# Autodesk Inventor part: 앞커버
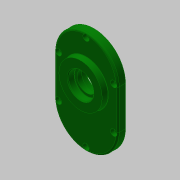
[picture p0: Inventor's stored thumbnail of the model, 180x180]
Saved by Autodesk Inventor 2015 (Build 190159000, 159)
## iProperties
Created: 2016-12
Part Number: 앞커버
Material: 알루미늄 6061
Document SubType Name: Modeling
Designer: mduedu
Density: 2.71 g/cm^3
Mass: 264.838 g
Surface Area: 264.105 cm^2
Volume: 97.726 cm^3
Appearance: 진녹색
Author: mduedu
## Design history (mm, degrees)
sketch "스케치1"
  geometry: L1 (40, -25)-(40, 25); L2 (-40, 25)-(-40, -25); L3 (-40, -25)-(40, 25); L4 (40, -25)-(-40, 25); A1 r 40 centre (0, 25) between (40, 25) and (-40, 25); A2 r 40 centre (0, -25) between (-40, -25) and (40, -25); 1 further point
  constraints: 8 end point, 4 point on circle, 4 tangent, 2 centre point, 2 midpoint, 1 parallel, 1 vertical
  dimensions: "d0" = 130 dimension on A2 A1; "d2" = 80 distance between parallel lines of L1 L2
extrude "돌출1" new body sketch "스케치1" distance "d3" = 10; taper "d4" = 0 deg
sketch "스케치2"
  geometry: C1 r 21 at (0, 11); 1 further point
  constraints: 1 centre point, 1 vertical alignment
  dimensions: "d5" = 42 diameter of C1; "d7" = 11 distance of C1.centre point (0, 0)
extrude "돌출2" join sketch "스케치2" distance "d8" = 7; taper "d9" = 0 deg
sketch "스케치3"
  geometry: C1 r 15 at (0, -33.1); C2 r 21 at (0, 11) reference; 1 further point
  constraints: 1 centre point, 1 vertical alignment
  dimensions: "d10" = 30 diameter of C1; "d71" = 44.1 distance of C1.centre C2.centre
extrude "돌출3" join sketch "스케치3" distance "d12" = 7; taper "d13" = 0 deg
sketch "스케치4"
  geometry: C1 r 28 at (0, 11); A1 r 21 centre (0, 11) between (8.978, -7.984) and (-8.978, -7.984) reference; 1 further point
  constraints: 1 centre point, 1 coincident
  dimensions: "d14" = 56 diameter of C1
extrude "돌출4" join sketch "스케치4" distance "d15" = 7; taper "d16" = -5 deg
hole "구멍1" diameter "d19" = 35; stored, may be unused: countersink angle "d23" = 90 deg, drill point angle "d25" = 0 deg; dims "d17" = 10, "d18" = 10, "d20" = 6, "d21" = 4, "d22" = 2, "d24" = 10
hole "구멍2" diameter "d28" = 22; stored, may be unused: countersink angle "d32" = 90 deg, drill point angle "d34" = 0 deg; dims "d26" = 10, "d27" = 10, "d29" = 6, "d30" = 4, "d31" = 2, "d33" = 7
hole "구멍3" diameter "d37" = 19; stored, may be unused: countersink angle "d41" = 90 deg, drill point angle "d43" = 0 deg; dims "d35" = 10, "d36" = 10, "d38" = 6, "d39" = 4, "d40" = 2, "d42" = 1
hole "구멍4" diameter "d46" = 32; stored, may be unused: countersink angle "d50" = 90 deg, drill point angle "d52" = 0 deg; dims "d44" = 10, "d45" = 10, "d47" = 6, "d48" = 4, "d49" = 2, "d51" = 8
hole "구멍5" diameter "d55" = 25; stored, may be unused: countersink angle "d59" = 90 deg, drill point angle "d61" = 0 deg; dims "d53" = 10, "d54" = 10, "d56" = 6, "d57" = 4, "d58" = 2, "d60" = 8
fillet "모깎기1" dims "d62" = 0.3
fillet "모깎기2" dims "d63" = 2
chamfer "모따기1" distance "d64" = 1; stored, may be unused: second distance "d65" = 2, angle "d66" = 45 deg
fillet "모깎기4" dims "d68" = 2
fillet "모깎기5" dims "d69" = 0.3
fillet "모깎기6" dims "d70" = 2
sketch "스케치5"
  geometry: L1 (-40, 25)-(-40, -25) reference; L2 (40, -25)-(40, 25) reference; L3 (35, 25)-(35, -25); L4 (-35, -25)-(-35, 25); A1 r 40 centre (0, 25) between (40, 25) and (-40, 25) reference; A2 r 40 centre (0, -25) between (-40, -25) and (40, -25) reference; A3 r 35 centre (0, 25) between (35, 25) and (-35, 25); A4 r 35 centre (0, -25) between (-35, -25) and (35, -25); 2 further points
  constraints: 5 point on circle, 4 end point, 2 centre point, 1 vertical alignment, 3 other
  dimensions: "d72" = 5 distance between parallel lines of L2 L3
sketch "스케치7"
  geometry: 1 further point
hole "구멍7" sketch "스케치7" at (0, 60) diameter "d80" = 4.5; stored, may be unused: countersink angle "d84" = 90 deg, drill point angle "d86" = 0 deg; dims "d81" = 6, "d82" = 8, "d83" = 4.6, "d85" = 8
node "솔리드1"
pattern_linear "직사각형 패턴1"
